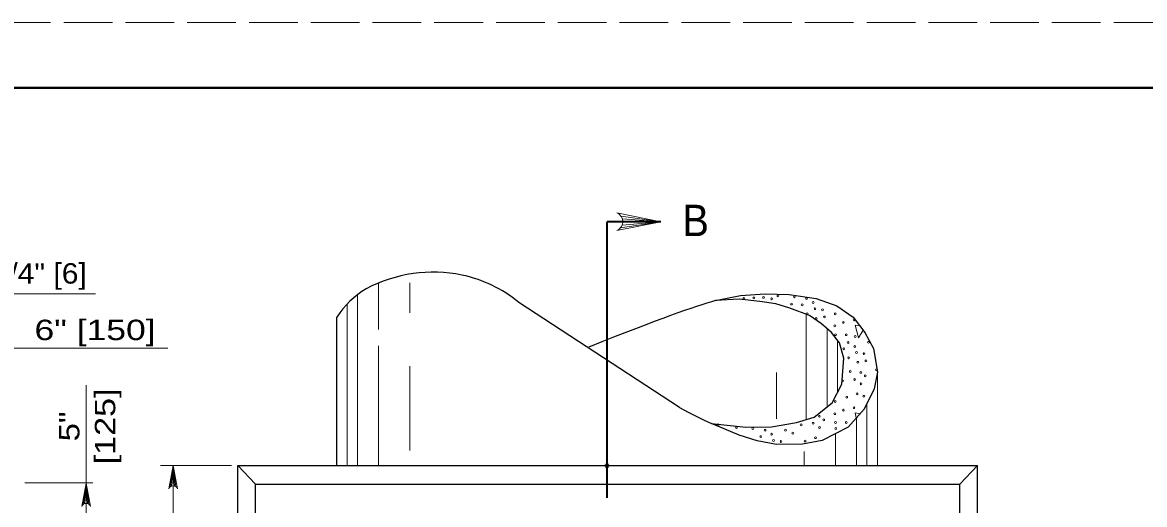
# Model space of a CAD drawing. Extents: x 1329.9 to 1363.9, y 715.5 to 737.5.
# Drawn here: x 1346.18 to 1354.76, y 733.81 to 737.5 of the extents above; entities that cross this region are included whole.
import ezdxf
from ezdxf.enums import TextEntityAlignment as Align

# ---------------------------------------------------------------- set-up
doc = ezdxf.new("R2010")
doc.units = 0
doc.header["$LTSCALE"] = 0.062
doc.header["$PDMODE"] = 32
doc.header["$PDSIZE"] = 0.031
doc.linetypes.add('LONG_DASHED', pattern=[7.5, 6, -1.5])
doc.layers.add('1', color=7, linetype='Continuous', lineweight=13)

msp = doc.modelspace()

# ---------------------------------------------------------------- linework, layer by layer
at = {"layer": '1', "lineweight": 25}
for p, q in [((1331.86333, 736.9975), (1363.36333, 736.9975)), ((1351.20408, 734.5515), (1349.977, 735.35592)), ((1348.58517, 734.1075), (1348.58517, 735.24217)), ((1347.83075, 734.1075), (1353.483, 734.1075)), ((1347.83075, 728.1235), (1347.83075, 734.1075)), ((1347.96533, 733.96508), (1347.83075, 734.1075)), ((1353.483, 734.1075), (1353.34842, 733.96508)), ((1353.483, 728.1235), (1353.483, 734.1075)), ((1347.96533, 733.96508), (1353.34842, 733.96508)), ((1347.96533, 728.26592), (1347.96533, 733.96508)), ((1353.34842, 728.26592), (1353.34842, 733.96508))]:
    msp.add_line(p, q, dxfattribs=at)
at = {"layer": '1'}
for p, q in [((1350.75792, 736.016), (1351.06258, 735.97333)), ((1350.76825, 735.99492), (1351.06258, 735.97333)), ((1350.75433, 735.92625), (1351.06258, 735.97333)), ((1350.766, 735.946), (1351.06258, 735.97333)), ((1350.77142, 735.97333), (1351.06258, 735.97333)), ((1348.90525, 735.14917), (1348.90525, 735.50442)), ((1349.14533, 735.27533), (1349.14533, 735.50442)), ((1345.68883, 735.42075), (1346.74308, 735.42075)), ((1348.74525, 734.1075), (1348.74525, 735.4155)), ((1348.66525, 734.1075), (1348.66525, 735.34292)), ((1351.54967, 735.37367), (1351.54183, 735.38183)), ((1352.17275, 734.45925), (1352.17275, 735.26467)), ((1352.33283, 734.557), (1352.33283, 735.15508)), ((1352.58308, 735.17558), (1352.54617, 735.18275)), ((1352.41283, 734.66783), (1352.41283, 735.0675)), ((1345.68883, 735.00675), (1347.29383, 735.00675)), ((1348.90525, 734.1075), (1348.90525, 735.02275)), ((1349.14533, 734.22325), (1349.14533, 734.869)), ((1351.946, 734.46458), (1351.946, 734.81958)), ((1352.7175, 734.1075), (1352.7175, 734.82125)), ((1346.67067, 733.48308), (1346.67067, 734.72233)), ((1352.6375, 734.1075), (1352.6375, 734.58517)), ((1352.54617, 734.51117), (1352.55608, 734.4735)), ((1352.583, 734.50392), (1352.54617, 734.51117)), ((1352.5575, 734.1075), (1352.5575, 734.47475)), ((1351.45992, 734.42417), (1351.4565, 734.428)), ((1351.494, 734.41033), (1351.47933, 734.42558)), ((1352.39742, 734.1075), (1352.39742, 734.35192)), ((1352.15733, 734.1075), (1352.15733, 734.21625)), ((1347.23817, 734.10725), (1347.782, 734.10725)), ((1347.31192, 733.94417), (1347.3355, 734.10725)), ((1347.32183, 733.95033), (1347.3355, 734.10725)), ((1347.3355, 733.95317), (1347.3355, 734.10725)), ((1347.34625, 733.9515), (1347.3355, 734.10725)), ((1347.35683, 733.94608), (1347.3355, 734.10725)), ((1347.3355, 732.60442), (1347.3355, 734.10725)), ((1346.20225, 733.97533), (1346.72133, 733.97533)), ((1346.64708, 733.80958), (1346.67067, 733.97267)), ((1346.657, 733.81575), (1346.67067, 733.97267)), ((1346.67067, 733.67733), (1346.67067, 733.97267)), ((1346.67067, 733.81858), (1346.67067, 733.97267)), ((1346.68142, 733.81692), (1346.67067, 733.97267)), ((1346.692, 733.81142), (1346.67067, 733.97267))]:
    msp.add_line(p, q, dxfattribs=at)
at = {"layer": '1', "lineweight": 35}
for p in [(1351.06258, 735.97333), (1350.65133, 733.8605)]:
    msp.add_line(p, (1350.65133, 735.97333), dxfattribs=at)
at = {"layer": '1', "linetype": 'LONG_DASHED'}
msp.add_lwpolyline([(1329.86333, 715.4975), (1363.86333, 715.4975), (1363.86333, 737.4975), (1329.86333, 737.4975)], close=True, dxfattribs=at)
at = {"layer": '1', "lineweight": 40}
msp.add_lwpolyline([(1331.86333, 736.9975), (1363.36333, 736.9975), (1363.36333, 715.9975), (1331.86333, 715.9975)], close=True, dxfattribs=at)
msp.add_lwpolyline([(1331.86333, 736.9975), (1363.36333, 736.9975), (1363.36333, 715.9975), (1331.86333, 715.9975)], close=True, dxfattribs=at)
at = {"layer": '1'}
for points in [[(1350.72608, 735.90608), (1351.06258, 735.97333), (1350.72608, 736.04067)], [(1351.44875, 734.42908), (1351.6605, 734.34133), (1351.79875, 734.29792), (1351.94675, 734.27017), (1352.14525, 734.27108), (1352.29633, 734.29933), (1352.49258, 734.40133), (1352.615, 734.54017), (1352.69208, 734.695), (1352.7175, 734.82125), (1352.6865, 735.00208), (1352.62117, 735.1265), (1352.53183, 735.24183), (1352.40642, 735.32908), (1352.24817, 735.38667), (1352.04317, 735.4155), (1351.859, 735.42142), (1351.67067, 735.40808), (1351.48092, 735.3695)], [(1351.48092, 735.3695), (1351.65967, 735.38042), (1351.8185, 735.36375), (1351.93983, 735.344), (1352.049, 735.31092), (1352.19833, 735.25508), (1352.28883, 735.19242), (1352.36667, 735.1265), (1352.42883, 735.04717), (1352.46008, 734.9285), (1352.44458, 734.73083), (1352.37283, 734.58875), (1352.23275, 734.47692), (1352.09883, 734.43725), (1351.90892, 734.40433), (1351.71258, 734.401), (1351.44875, 734.42908)], [(1352.54617, 735.18275), (1352.57183, 735.08542), (1352.60833, 735.143)], [(1347.30183, 733.92917), (1347.3355, 734.10725), (1347.36917, 733.92917)], [(1346.637, 733.79458), (1346.67067, 733.97267), (1346.70433, 733.79458)]]:
    msp.add_lwpolyline(points, dxfattribs=at)
at = {"layer": '1', "lineweight": 25}
for points in [[(1351.48092, 735.3695), (1351.67067, 735.40808), (1351.859, 735.42142), (1352.04317, 735.4155), (1352.24817, 735.38667), (1352.40642, 735.32908), (1352.53183, 735.24183), (1352.62117, 735.1265), (1352.6865, 735.00208), (1352.7175, 734.82125), (1352.69208, 734.695), (1352.615, 734.54017), (1352.49258, 734.40133), (1352.29633, 734.29933), (1352.14525, 734.27108), (1351.94675, 734.27017), (1351.79875, 734.29792), (1351.6605, 734.34133), (1351.44875, 734.42908)], [(1351.44875, 734.42908), (1351.71258, 734.401), (1351.90892, 734.40433), (1352.09883, 734.43725), (1352.23275, 734.47692), (1352.37283, 734.58875), (1352.44458, 734.73083), (1352.46008, 734.9285), (1352.42883, 735.04717), (1352.36667, 735.1265), (1352.28883, 735.19242), (1352.19833, 735.25508), (1352.049, 735.31092), (1351.93983, 735.344), (1351.8185, 735.36375), (1351.65967, 735.38042), (1351.48092, 735.3695)]]:
    msp.add_lwpolyline(points, dxfattribs=at)
at = {"layer": '1'}
msp.add_lwpolyline([(1351.48092, 735.3695), (1351.65967, 735.38042), (1351.8185, 735.36375), (1351.93983, 735.344), (1352.049, 735.31092), (1352.19833, 735.25508), (1352.28883, 735.19242), (1352.36667, 735.1265), (1352.42883, 735.04717), (1352.46008, 734.9285), (1352.44458, 734.73083), (1352.37283, 734.58875), (1352.23275, 734.47692), (1352.09883, 734.43725), (1351.90892, 734.40433), (1351.71258, 734.401), (1351.44875, 734.42908), (1351.6605, 734.34133), (1351.79875, 734.29792), (1351.94675, 734.27017), (1352.14525, 734.27108), (1352.29633, 734.29933), (1352.49258, 734.40133), (1352.615, 734.54017), (1352.69208, 734.695), (1352.7175, 734.82125), (1352.6865, 735.00208), (1352.62117, 735.1265), (1352.53183, 735.24183), (1352.40642, 735.32908), (1352.24817, 735.38667), (1352.04317, 735.4155), (1351.859, 735.42142), (1351.67067, 735.40808)], close=True, dxfattribs=at)
msp.add_arc((1350.69893, 735.97343), 0.07261, 292.08605, 67.91218, dxfattribs=at)
at = {"layer": '1', "lineweight": 25}
for centre, major_axis, start_param, end_param in [((1349.32237, 734.36705), (0, 1.22023), 6.0913628, 6.7427401), ((1349.34034, 734.48343), (0, 1.10247), 5.6254463, 6.0881824), ((1349.15573, 734.82122), (0, 0.73619), 0.5184487, 0.9622613)]:
    msp.add_ellipse(centre, major_axis=major_axis, ratio=0.944544, start_param=start_param, end_param=end_param, dxfattribs=at)
at = {"layer": '1'}
for centre in [(1351.69739, 735.3867), (1351.77299, 735.38987), (1351.84698, 735.39446), (1351.95723, 735.40545), (1352.08252, 735.39851), (1351.90897, 735.38268), (1352.06121, 735.34326), (1352.14247, 735.33683), (1352.17594, 735.38491), (1352.22642, 735.35497), (1352.24017, 735.30784), (1352.18017, 735.26793), (1352.25037, 735.23345), (1352.29753, 735.29961), (1352.31207, 735.24437), (1352.39517, 735.26877), (1352.5385, 735.22226), (1352.39206, 735.17603), (1352.45708, 735.20323), (1352.39718, 735.10892), (1352.47944, 735.10892), (1352.49314, 735.04909), (1352.54706, 735.09532), (1352.64899, 735.05088), (1352.45967, 735.00101), (1352.54362, 735.01914), (1352.55737, 734.97202), (1352.61473, 734.96379), (1352.49737, 734.93211), (1352.56757, 734.89763), (1352.62927, 734.90855), (1352.50995, 734.82756), (1352.59078, 734.82056), (1352.62446, 734.79397), (1352.70925, 734.84021), (1352.45174, 734.75496), (1352.54336, 734.76677), (1352.59163, 734.73381), (1352.48283, 734.63138), (1352.56165, 734.65673), (1352.61388, 734.6377), (1352.39517, 734.59713), (1352.45708, 734.53158), (1352.5385, 734.55061), (1352.27358, 734.48474), (1352.30726, 734.45815), (1352.39206, 734.50438), (1351.50014, 734.41914), (1351.64003, 734.39798), (1351.76532, 734.39104), (1351.85874, 734.37744), (1352.01459, 734.37923), (1352.13454, 734.41914), (1352.22616, 734.43095), (1352.27443, 734.39798), (1352.39718, 734.43727), (1352.39972, 734.39104), (1352.47944, 734.43727), (1351.82527, 734.32936), (1351.90923, 734.3475), (1351.92297, 734.30037), (1351.98033, 734.29214), (1352.0711, 734.35567), (1352.16563, 734.29556), (1352.24445, 734.32091)]:
    msp.add_ellipse(centre, major_axis=(0, 0.00718), ratio=0.944544, dxfattribs=at)
for centre in [(1347.3355, 733.91474), (1346.67066, 733.78014)]:
    msp.add_ellipse(centre, major_axis=(0, 0.03844), ratio=0.944544, start_param=5.0978942, end_param=7.4685073, dxfattribs=at)
at = {"layer": '1', "lineweight": 25}
for points in [[(1351.48092, 735.3695), (1351.31592, 735.32425), (1351.05092, 735.22942), (1350.51233, 735.01467)], [(1351.20408, 734.5515), (1351.29425, 734.50325), (1351.37567, 734.46275), (1351.44875, 734.42908)]]:
    msp.add_open_spline(points, degree=3, dxfattribs=at)
at = {"layer": '1'}
msp.add_point((1350.65133, 734.1075), dxfattribs=at)

# ---------------------------------------------------------------- texts
for s, height, width, p in [('B', 0.24, 0.95, (1351.32825, 735.86292)), ('1/4" [6]', 0.156, 1.1, (1346.31588, 735.49975))]:
    msp.add_text(s, height=height, dxfattribs=dict(at, width=width)).set_placement(p, align=Align.CENTER)
at = {"layer": '1', "width": 1.3}
msp.add_text('6" [150]', height=0.156, dxfattribs=at).set_placement((1346.27583, 735.06767))
at = {"layer": '1'}
for s, width, p in [('[125]', 1.25, (1346.89308, 734.4075)), ('5"', 1.2, (1346.619, 734.40754))]:
    msp.add_text(s, height=0.156, rotation=90, dxfattribs=dict(at, width=width)).set_placement(p, align=Align.CENTER)

doc.saveas('drawing.dxf')
